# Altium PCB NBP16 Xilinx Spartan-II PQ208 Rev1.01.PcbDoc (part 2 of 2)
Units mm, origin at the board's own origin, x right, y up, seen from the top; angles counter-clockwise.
Board outline 69 x 80.99 mm, 2 copper layers (Top Layer, Bottom Layer); 48 components, 186 nets, 518 pads, 188 vias.
Unrouted connection lines stored in the file: 1.
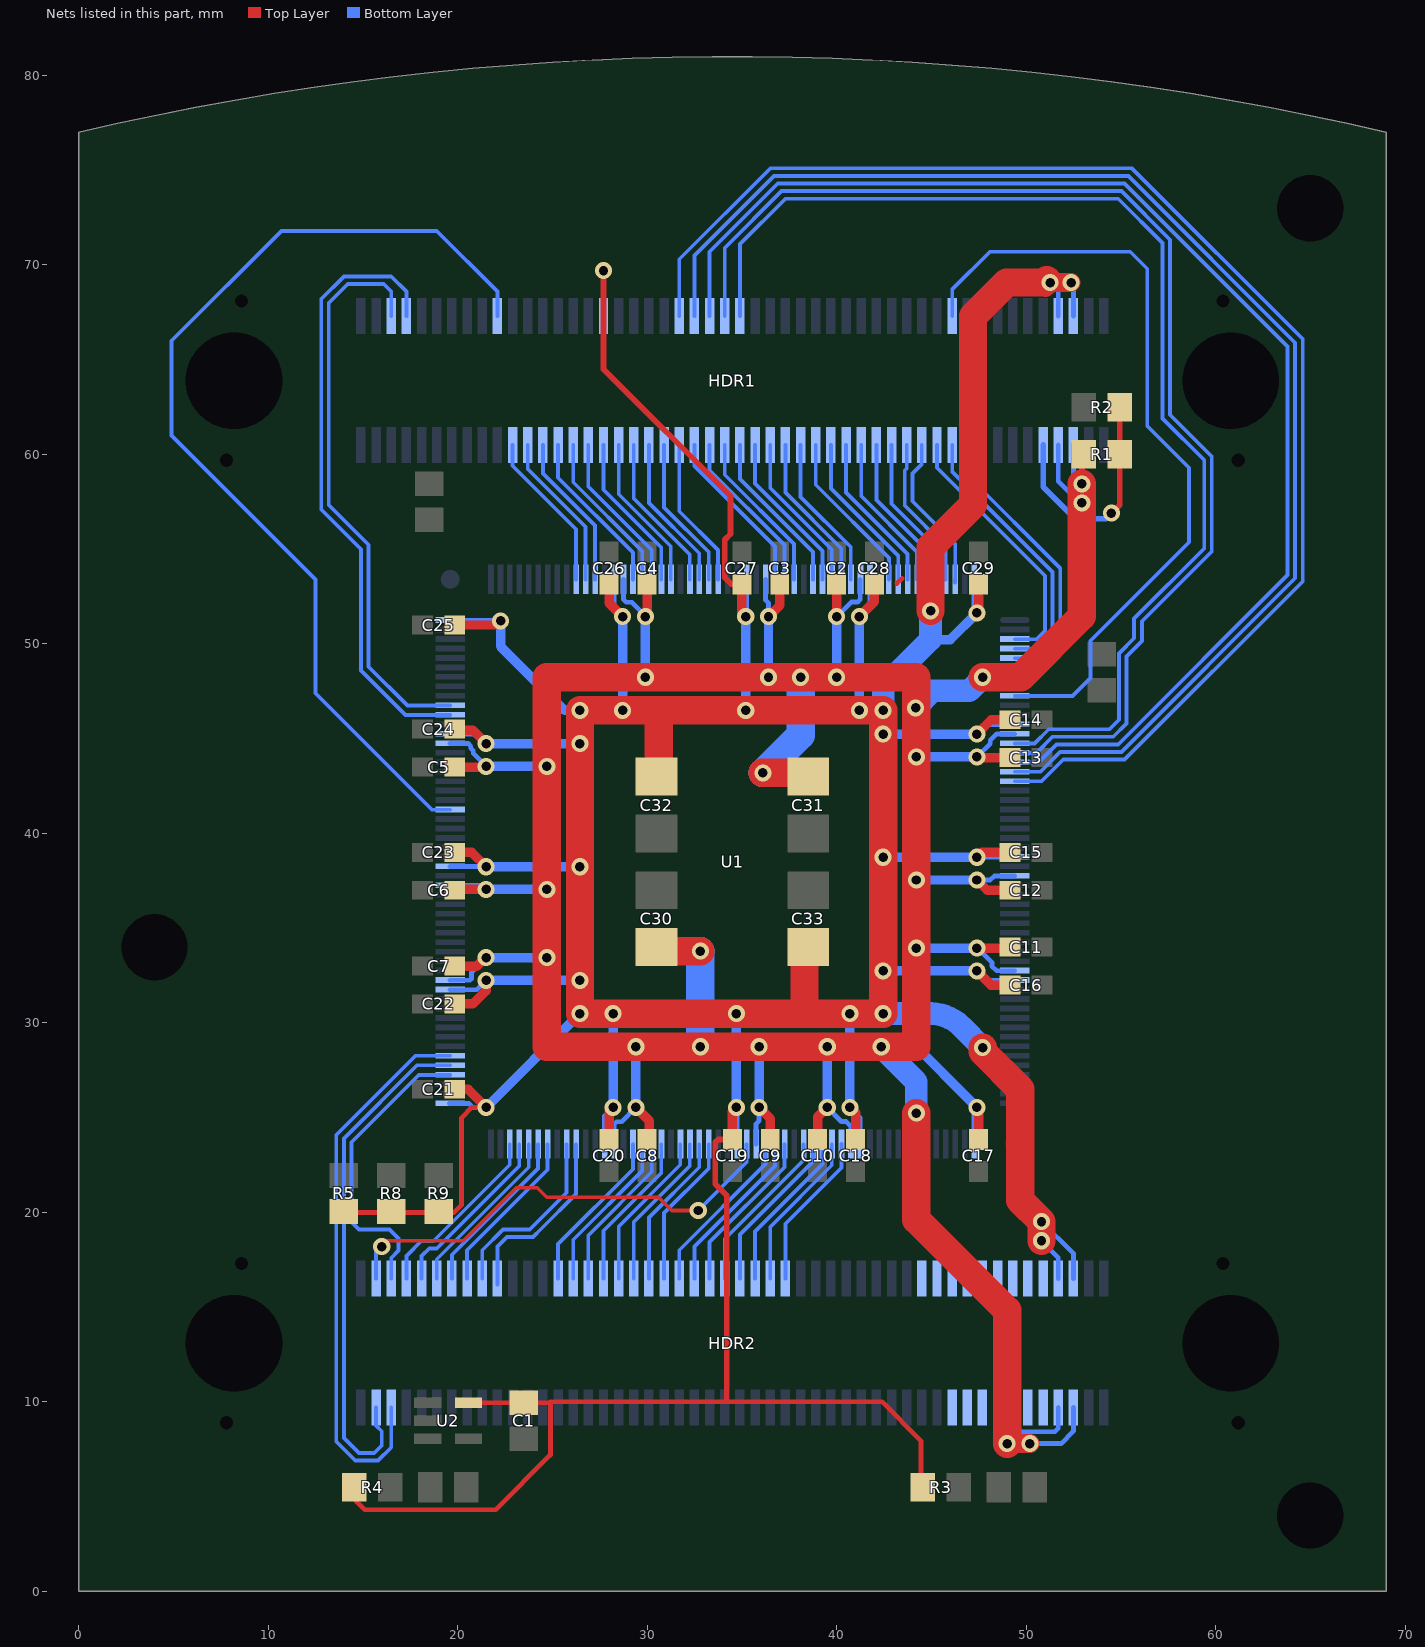
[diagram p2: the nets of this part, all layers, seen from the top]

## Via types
v1: diameter 0.9, hole 0.5, Top Layer to Bottom Layer, tented both sides, 188 vias

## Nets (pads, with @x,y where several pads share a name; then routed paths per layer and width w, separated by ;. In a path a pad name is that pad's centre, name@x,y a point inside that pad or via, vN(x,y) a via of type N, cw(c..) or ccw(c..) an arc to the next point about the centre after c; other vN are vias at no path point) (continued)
NEXUS_TMS: HDR1.80 U1.9 | length 42
  Bottom Layer w0.2: HDR1.80@46.1,67.3 46.1,68.7 48.1,70.7 55.5,70.7 56.4,69.8 56.4,61.5 58.6,59.3 58.6,55.369 53.4,50.169 53.4,48.2 52.45,47.25 U1.9@49.4,47.25
RAM0_DATA0: HDR2.42 U1.81 | length 8.1
  Bottom Layer w0.2: HDR2.42@30.9,16.5 30.9,19.966 33.25,22.316 U1.81@33.25,23.6
RAM0_DATA1: HDR2.40 U1.82 | length 8.2
  Bottom Layer w0.2: HDR2.40@30.1,16.5 30.1,19.731 32.75,22.381 U1.82@32.75,23.6
RAM0_DATA2: HDR2.38 U1.83 | length 8.3
  Bottom Layer w0.2: HDR2.38@29.3,16.5 29.3,19.497 32.25,22.447 U1.83@32.25,23.6
RAM0_DATA3: HDR2.36 U1.84 | length 8.4
  Bottom Layer w0.2: HDR2.36@28.5,16.5 28.5,19.263 31.75,22.513 U1.84@31.75,23.6
RAM0_DATA4: HDR2.34 U1.86 | length 8.4
  Bottom Layer w0.2: HDR2.34@27.7,16.5 27.7,19.028 30.75,22.078 U1.86@30.75,23.6
RAM0_DATA5: HDR2.32 U1.87 | length 8.5
  Bottom Layer w0.2: HDR2.32@26.9,16.5 26.9,18.794 30.25,22.144 U1.87@30.25,23.6
RAM0_DATA6: HDR2.30 U1.88 | length 8.6
  Bottom Layer w0.2: HDR2.30@26.1,16.5 26.1,18.56 29.75,22.21 U1.88@29.75,23.6
RAM0_DATA7: HDR2.28 U1.89 | length 8.7
  Bottom Layer w0.2: HDR2.28@25.3,16.5 25.3,18.325 29.25,22.275 U1.89@29.25,23.6
RAM0_OE: HDR1.41 U1.180 | length 8.1
  Bottom Layer w0.2: HDR1.41@30.9,60.5 30.9,57.2 33.25,54.85 U1.180@33.25,53.4
RAM0_WE: HDR1.79 U1.4 | length 14.5
  Bottom Layer w0.2: HDR1.79@46.1,60.5 46.1,59.1 51.4,53.8 51.4,50.5 50.65,49.75 U1.4@49.4,49.75
RAM1_DATA0: HDR1.45 U1.187 | length 8.9
  Bottom Layer w0.2: HDR1.45@32.5,60.5 32.5,59.4 36.75,55.15 U1.187@36.75,53.4
RAM1_DATA1: HDR1.49 U1.189 | length 8.6
  Bottom Layer w0.2: HDR1.49@34.1,60.5 34.1,58.931 37.75,55.281 U1.189@37.75,53.4
RAM1_DATA2: HDR1.53 U1.192 | length 8.6
  Bottom Layer w0.2: HDR1.53@35.7,60.5 35.7,58.463 39.25,54.913 U1.192@39.25,53.4
RAM1_DATA3: HDR1.57 U1.194 | length 8.3
  Bottom Layer w0.2: HDR1.57@37.3,60.5 37.3,57.994 40.25,55.044 U1.194@40.25,53.4
RAM1_DATA4: HDR1.55 U1.193 | length 8.4
  Bottom Layer w0.2: HDR1.55@36.5,60.5 36.5,58.228 39.75,54.978 U1.193@39.75,53.4
RAM1_DATA5: HDR1.51 U1.191 | length 8.7
  Bottom Layer w0.2: HDR1.51@34.9,60.5 34.9,58.697 38.75,54.847 U1.191@38.75,53.4
RAM1_DATA6: HDR1.47 U1.188 | length 8.7
  Bottom Layer w0.2: HDR1.47@33.3,60.5 33.3,59.166 37.25,55.216 U1.188@37.25,53.4
RAM1_DATA7: HDR1.43 U1.181 | length 7.9
  Bottom Layer w0.2: HDR1.43@31.7,60.5 31.7,57 33.75,54.95 U1.181@33.75,53.4
RAM1_OE: HDR1.39 U1.179 | length 8.2
  Bottom Layer w0.2: HDR1.39@30.1,60.5 30.1,57.434 32.75,54.784 U1.179@32.75,53.4
RAM1_WE: HDR1.61 U1.199 | length 8.7
  Bottom Layer w0.2: HDR1.61@38.9,60.5 38.9,58.4 42.76,54.54 U1.199@42.76,53.411 ; U1.199@42.75,53.4 U1.199@42.75,53.411
RAM_ADDR0: HDR1.21 U1.166 | length 8.5
  Bottom Layer w0.2: HDR1.21@22.9,60.5 22.9,59.4 26.25,56.05 U1.166@26.25,53.4
RAM_ADDR1: HDR1.25 U1.168 | length 8.2
  Bottom Layer w0.2: HDR1.25@24.5,60.5 24.5,59 27.25,56.25 U1.168@27.25,53.4
RAM_ADDR2: HDR1.29 U1.173 | length 8.6
  Bottom Layer w0.2: HDR1.29@26.1,60.5 26.1,58.534 29.75,54.884 U1.173@29.75,53.4
RAM_ADDR3: HDR1.33 U1.175 | length 8.4
  Bottom Layer w0.2: HDR1.33@27.7,60.5 27.7,58.137 30.75,55.087 U1.175@30.75,53.4
RAM_ADDR4: HDR1.65 U1.201 | length 8.4
  Bottom Layer w0.2: HDR1.65@40.5,60.5 40.5,58 43.75,54.75 U1.201@43.75,53.4
RAM_ADDR5: HDR1.69 U1.203 | length 8.2
  Bottom Layer w0.2: HDR1.69@42.1,60.5 42.1,57.6 44.75,54.95 U1.203@44.75,53.4
RAM_ADDR6: HDR1.73 U1.205 | length 8
  Bottom Layer w0.2: HDR1.73@43.7,60.5 43.7,59.266 43.6,59.166 43.6,57.3 45.75,55.15 U1.205@45.75,53.4
RAM_ADDR7: HDR1.77 U1.3 | length 13.9
  Bottom Layer w0.2: HDR1.77@45.3,60.5 45.3,59.3 51,53.6 51,50.7 50.55,50.25 U1.3@49.4,50.25
RAM_ADDR8: HDR1.75 U1.206 | length 8.4
  Bottom Layer w0.2: HDR1.75@44.5,60.5 44.5,59.5 44,59 44,57.534 46.26,55.275 U1.206@46.26,53.411 ; U1.206@46.25,53.25 U1.206@46.25,53.411
RAM_ADDR9: HDR1.71 U1.204 | length 8.1
  Bottom Layer w0.2: HDR1.71@42.9,60.5 42.9,57.4 45.25,55.05 U1.204@45.25,53.4
RAM_ADDR10: HDR1.67 U1.202 | length 8.3
  Bottom Layer w0.2: HDR1.67@41.3,60.5 41.3,57.8 44.25,54.85 U1.202@44.25,53.4
RAM_ADDR11: HDR1.63 U1.200 | length 8.6
  Bottom Layer w0.2: HDR1.63@39.7,60.5 39.7,58.2 43.26,54.64 U1.200@43.26,53.411 ; U1.200@43.25,53.4 U1.200@43.25,53.411
RAM_ADDR12: HDR1.59 U1.195 | length 8.2
  Bottom Layer w0.2: HDR1.59@38.1,60.5 38.1,57.76 40.75,55.11 U1.195@40.75,53.4
RAM_ADDR13: HDR1.35 U1.176 | length 8.2
  Bottom Layer w0.2: HDR1.35@28.5,60.5 28.5,57.903 31.25,55.153 U1.176@31.25,53.4
RAM_ADDR14: HDR1.31 U1.174 | length 8.5
  Bottom Layer w0.2: HDR1.31@26.9,60.5 26.9,58.3 30.25,54.95 U1.174@30.25,53.4
RAM_ADDR15: HDR1.27 U1.172 | length 8.7
  Bottom Layer w0.2: HDR1.27@25.3,60.5 25.3,58.769 29.25,54.819 U1.172@29.25,53.4
RAM_ADDR16: HDR1.23 U1.167 | length 8.4
  Bottom Layer w0.2: HDR1.23@23.7,60.5 23.7,59.234 26.75,56.184 U1.167@26.75,53.4
RAM_CS: HDR1.37 U1.178 | length 8.3
  Bottom Layer w0.2: HDR1.37@29.3,60.5 29.3,57.669 32.25,54.719 U1.178@32.25,53.4
RED0: HDR1.6 U1.147 | length 30.4
  Bottom Layer w0.2: HDR1.6@16.5,67.3 16.5,68.6 16.1,69 14.2,69 13.2,68 13.2,57.334 15.3,55.234 15.3,48.8 17.35,46.75 U1.147@19.6,46.75
RED1: HDR1.8 U1.146 | length 32.8
  Bottom Layer w0.2: HDR1.8@17.3,67.3 17.3,68.6 16.5,69.4 14,69.4 12.8,68.2 12.8,57.1 14.9,55 14.9,48.6 17.25,46.25 U1.146@19.6,46.25
REF_CLK: HDR2.4 U1.77 | length 24.9
  Top Layer w0.2: v1(15.996,18.196) 16.3,18.5 20.3,18.5 20.7,18.9 23.1,21.3 24.2,21.3 24.7,20.8 30.6,20.8 31.3,20.1 v1(32.7,20.1)
  Bottom Layer w0.2: HDR2.4@15.7,16.5 15.7,17.9 v1(15.996,18.196) ; v1(32.7,20.1) 35.25,22.65 U1.77@35.25,23.6
SCL: HDR2.5 U1.110 | length 29.6
  Bottom Layer w0.2: HDR2.5@16.5,9.7 16.5,7.6 15.8,6.9 14.6,6.9 13.6,7.9 13.6,24.1 17.761,28.261 U1.110@19.61,28.261
SDA: HDR2.3 U1.109 | length 27.6
  Bottom Layer w0.2: HDR2.3@15.7,9.7 15.7,8.75 16,8.45 16,7.7 15.6,7.3 14.8,7.3 14,8.1 14,23.9 17.861,27.761 U1.109@19.61,27.761
SP0: HDR2.79
SP1: HDR2.81
SP2: HDR2.83
SP3: HDR2.85
SP4: HDR2.87
SP5: HDR2.89
SP6: HDR2.91
SP7: HDR2.90
SP8: HDR2.92
SP9: HDR2.88
SP10: HDR2.86
SP11: HDR2.84
SP12: HDR2.82
SP13: HDR2.80
SP14: HDR2.78
SP15: HDR2.76
SPI_CLK: HDR1.46 U1.17 | length 71.8
  Bottom Layer w0.2: HDR1.46@32.5,67.3 32.5,70.5 36.7,74.7 55.4,74.7 64.2,65.9 64.2,53.466 55.034,44.3 51.8,44.3 50.75,43.25 U1.17@49.4,43.25
SPI_DIN: HDR1.44 U1.18 | length 74
  Bottom Layer w0.2: HDR1.44@31.7,67.3 31.7,70.3 36.5,75.1 55.6,75.1 64.6,66.1 64.6,53.3 55.2,43.9 51.966,43.9 50.816,42.75 U1.18@49.4,42.75
SPI_DOUT: HDR1.50 U1.15 | length 64.3
  Bottom Layer w0.2: HDR1.50@34.1,67.3 34.1,70.9 37.1,73.9 55.034,73.9 57.6,71.334 57.6,62.1 59.8,59.9 59.8,54.872 56.126,51.197 56.126,50.16 55.3,49.334 55.3,45.8 54.6,45.1 51.4,45.1 50.55,44.25 U1.15@49.4,44.25
SPI_MODE: HDR1.52 U1.14 | length 62
  Bottom Layer w0.2: HDR1.52@34.9,67.3 34.9,71.1 37.3,73.5 54.869,73.5 57.2,71.169 57.2,61.9 59.4,59.7 59.4,55.037 55.7,51.337 55.7,50.3 54.9,49.5 54.9,46 54.4,45.5 51.2,45.5 50.45,44.75 U1.14@49.4,44.75
SPI_SEL: HDR1.48 U1.16 | length 69.5
  Bottom Layer w0.2: HDR1.48@33.3,67.3 33.3,70.7 36.9,74.3 55.2,74.3 63.8,65.7 63.8,53.631 54.869,44.7 51.6,44.7 50.65,43.75 U1.16@49.41,43.75
SW0: HDR2.44 U1.75 | length 9
  Bottom Layer w0.2: HDR2.44@31.7,16.5 31.7,18 36.25,22.55 U1.75@36.25,23.6
SW1: HDR2.46 U1.74 | length 8.9
  Bottom Layer w0.2: HDR2.46@32.5,16.5 32.5,18.2 36.75,22.45 U1.74@36.75,23.6
SW2: HDR2.48 U1.73 | length 8.7
  Bottom Layer w0.2: HDR2.48@33.3,16.5 33.3,18.434 37.25,22.384 U1.73@37.25,23.6
SW3: HDR2.50 U1.71 | length 8.8
  Bottom Layer w0.2: HDR2.50@34.1,16.5 34.1,18.6 38.25,22.75 U1.71@38.25,23.6
SW4: HDR2.52 U1.70 | length 8.7
  Bottom Layer w0.2: HDR2.52@34.9,16.5 34.9,18.834 38.75,22.684 U1.70@38.75,23.6
SW5: HDR2.54 U1.69 | length 8.6
  Bottom Layer w0.2: HDR2.54@35.7,16.5 35.7,19 39.25,22.55 U1.69@39.25,23.6
SW6: HDR2.56 U1.68 | length 8.4
  Bottom Layer w0.2: HDR2.56@36.5,16.5 36.5,19.234 39.75,22.484 U1.68@39.75,23.6
SW7: HDR2.58 U1.67 | length 8.3
  Bottom Layer w0.2: HDR2.58@37.3,16.5 37.3,19.4 40.26,22.36 U1.67@40.26,23.611
SWC0: HDR2.18 U1.96 | length 9.8
  Bottom Layer w0.2: HDR2.18@21.3,16.5 21.3,18 22.4,19.1 23.812,19.1 25.75,21.038 U1.96@25.75,23.6
SWC1: HDR2.16 U1.98 | length 8.9
  Bottom Layer w0.2: HDR2.16@20.5,16.5 20.5,18 24.75,22.25 U1.98@24.75,23.6
SWC2: HDR2.14 U1.99 | length 9
  Bottom Layer w0.2: HDR2.14@19.7,16.5 19.7,17.766 24.25,22.316 U1.99@24.25,23.6
SWC3: HDR2.6 U1.108 | length 16
  Bottom Layer w0.2: HDR2.6@16.5,16.5 16.5,17.6 16.885,17.985 16.885,18.615 16.4,19.1 14.8,19.1 14.4,19.5 14.4,23.7 17.95,27.25 U1.108@19.6,27.25
SWR0: HDR2.20 U1.95 | length 9.9
  Bottom Layer w0.2: HDR2.20@22.1,16.2 HDR2.20@22.1,16.5 22.1,18.2 22.6,18.7 23.977,18.7 24.412,19.135 26.25,20.973 U1.95@26.25,23.6
SWR1: HDR2.12 U1.100 | length 9.1
  Bottom Layer w0.2: HDR2.12@18.9,16.5 18.9,17.531 23.75,22.381 U1.100@23.75,23.6
SWR2: HDR2.10 U1.101 | length 9.5
  Bottom Layer w0.2: HDR2.10@18.1,16.5 18.1,17.7 18.5,18.1 18.903,18.1 23.25,22.447 U1.101@23.25,23.6
SWR3: HDR2.8 U1.102 | length 9.7
  Bottom Layer w0.2: HDR2.8@17.3,16.5 17.3,17.7 18.1,18.5 18.737,18.5 22.75,22.513 U1.102@22.75,23.6
TEST: HDR1.81 U1.5 | length 15.1
  Bottom Layer w0.2: HDR1.81@46.9,60.5 46.9,58.9 51.8,54 51.8,50.3 50.75,49.25 U1.5@49.4,49.25
VCC: C1.2 C14.1 C15.1 C16.1 C17.2 C18.2 C19.2 C20.2 C21.2 C22.1 C23.1 C24.1 C25.2 C26.2 C27.2 C28.2 C29.2 C32.1 C33.1 HDR1.34 HDR1.94 HDR1.96 HDR2.94 HDR2.96 R3.1 R4.2 R5.1 R8.1 R9.1 U1.12 U1.26 U1.39 U1.53 U1.65 U1.78 U1.92 U1.105 U1.117 U1.130 U1.144 U1.156 U1.170 U1.184 U1.197 U1.208 U2.5 | length 368.1
  Top Layer w0.25: R5.1@13.708,19.992 19.808,19.992 20.208,20.392 20.208,24.992 20.758,25.542 v1(21.508,25.542) ; R4.2@14.55,5.497 14.55,4.85 15.1,4.3 22,4.3 24.9,7.2 24.9,10 ; U2.5@20.575,9.95 C1.2@23.497,9.95 24.85,9.95 24.9,10 ; 43.189,53.192 43.449,53.452 ; R3.1@44.45,5.5 R3.1@44.45,5.503 ; R3.1@44.55,5.503 44.45,5.602 44.45,7.95 42.4,10 24.9,10
  Top Layer w0.3: v1(27.7,69.7) 27.701,64.499 34.4,57.8 34.4,55.8 34.1,55.5 34.1,53.5 34.45,53.15 C27.2@35,53.15 ; 34.2,10.05 34.2,20.9 33.6,21.5 33.6,23.7 33.75,23.85 C19.2@34.5,23.85
  Top Layer w0.5: C24.1@19.758,45.442 20.808,45.442 v1(21.508,44.742) ; C21.2@19.85,26.5 20.55,26.5 v1(21.508,25.542) ; C22.1@19.85,31 20.8,31 21.508,31.708 v1(21.508,32.242) ; C23.1@19.85,39 20.75,39 v1(21.508,38.242) ; C25.2@19.85,51 22.048,51 v1(22.265,51.217) ; C20.2@28,23.85 28,25.334 v1(28.208,25.542) ; C26.2@28.008,53.192 28.008,52.142 v1(28.708,51.442) ; C19.2@34.5,23.85 34.5,25.334 v1(34.708,25.542) ; C27.2@35,53.15 35,51.65 v1(35.208,51.442) ; v1(40.708,25.542) 41,25.25 C18.2@41,23.85 ; v1(41.208,51.442) 42,52.234 C28.2@42,53.15 ; v1(47.408,25.542) 47.5,25.45 C17.2@47.5,23.85 ; v1(47.408,32.742) 48.15,32 C16.1@49.15,32 ; v1(47.408,38.742) 47.666,39 C15.1@49.15,39 ; v1(47.408,45.242) 48.166,46 C14.1@49.15,46 ; v1(47.408,51.642) 47.5,51.734 C29.2@47.5,53.15
  Top Layer w1: v1@51.018,68.819 51.25,69.05 v1(51.275,69.075) v1(52.375,69.075)
  Top Layer w1.5: C32.1@30.608,43.192 30.608,46.492 ; 38.308,30.492 C33.1@38.308,33.792 ; v1(44.958,51.742) 44.958,55.098 47.2,57.34 47.2,67.3 48.975,69.075 50.975,69.075 v1@51.1,69.2 ; v1(47.708,28.692) 47.708,28.489 49.7,26.497 49.7,20.633 v1(50.815,19.518) v1(50.815,18.502) ; v1(26.458,30.492) v1(42.458,30.492) v1(42.458,46.492) v1(26.458,46.492) v1(26.458,30.492)
  Bottom Layer w0.25: U1.105@19.558,25.742 20.608,25.742 20.808,25.542 v1(21.508,25.542) ; U1.117@19.6,31.75 21.016,31.75 v1(21.508,32.242) ; U1.130@19.6,38.25 21.5,38.25 v1(21.508,38.242) ; U1.144@19.6,45.25 21,45.25 v1(21.508,44.742) ; U1.156@19.6,51.25 22.233,51.25 v1(22.265,51.217) v1@21.96,51.242 ; HDR1.34@27.7,67.3 v1(27.7,69.7) ; U1.92@27.75,23.6 27.75,25.084 v1(28.208,25.542) ; U1.170@28.25,53.4 28.25,51.9 v1(28.708,51.442) ; v1(34.708,25.542) 34.75,25.5 U1.78@34.75,23.6 ; v1(35.208,51.442) 35.25,51.484 U1.184@35.25,53.4 ; v1(40.708,25.542) 41.25,25 U1.65@41.25,23.6 ; v1(41.208,51.442) 41.75,51.984 U1.197@41.75,53.4 ; U1.53@47.25,23.6 47.25,25.384 v1(47.408,25.542) ; U1.208@47.25,53.4 47.25,51.8 v1(47.408,51.642) ; v1(47.408,32.742) 47.9,32.25 U1.39@49.4,32.25 ; v1(47.408,38.742) U1.26@49.392,38.742 ; v1(47.408,45.242) 47.916,45.75 U1.12@49.4,45.75 ; v1(50.815,18.502) 51.7,17.617 HDR2.94@51.7,16.5 ; v1(50.815,19.518) 52.5,17.833 HDR2.96@52.5,16.5 ; v1(51.275,69.075) 51.7,68.65 HDR1.94@51.7,67.3 ; v1(52.375,69.075) 52.5,68.95 HDR1.96@52.5,67.3
  Bottom Layer w0.5: v1(21.508,25.542) v1(26.458,30.492) ; v1(21.508,32.242) v1(26.458,32.242) ; v1(21.508,38.242) v1(26.458,38.242) ; v1(21.508,44.742) v1(26.458,44.742) ; v1(22.265,51.217) 22.265,49.871 25.644,46.492 v1(26.458,46.492) ; v1(28.208,25.542) v1(28.208,30.492) ; v1(28.708,46.492) v1(28.708,51.442) ; v1(34.708,25.542) v1(34.708,30.492) ; v1(35.208,46.492) v1(35.208,51.442) ; v1(40.708,25.542) v1(40.708,30.492) ; v1(41.208,46.492) v1(41.208,51.442) ; v1(42.458,32.742) v1(47.408,32.742) ; v1(42.458,38.742) v1(47.408,38.742) ; v1(42.458,45.242) v1(47.408,45.242) ; 43.808,30.492 43.808,29.142 v1(47.408,25.542) ; 44.958,50.233 45.999,50.233 v1(47.408,51.642)
  Bottom Layer w1.2: v1(42.458,30.492) 44.955,30.492 cw(c44.955,28.192) 46.582,29.819 v1(47.708,28.692) ; v1(42.458,46.492) 42.458,47.733 44.958,50.233 v1(44.958,51.742)
VCCINT: C2.1 C3.1 C4.1 C5.1 C6.1 C7.1 C8.1 C9.1 C10.1 C11.1 C12.1 C13.1 C30.1 C31.1 HDR1.93 HDR1.95 HDR2.93 HDR2.95 R1.1 U1.13 U1.28 U1.38 U1.66 U1.76 U1.91 U1.118 U1.128 U1.143 U1.171 U1.186 U1.196 | length 244.3
  Top Layer w0.3: v1(52.95,58.45) 52.95,59.903 R1.1@53.05,60.003
  Top Layer w0.5: C7.1@19.85,33 21.022,33 v1@21.465,33.442 ; C6.1@19.85,37 19.892,37.042 v1(21.508,37.042) ; C5.1@19.85,43.5 21.466,43.5 v1(21.508,43.542) ; v1(29.408,25.542) 30.108,24.842 C8.1@30.108,23.792 ; v1(29.908,51.442) 30,51.534 C4.1@30,53.15 ; v1(35.908,25.542) 36.5,24.95 C9.1@36.5,23.85 ; v1(36.408,51.442) 37,52.034 C3.1@37,53.15 ; C10.1@39,23.85 39,25.034 v1(39.508,25.542) ; v1@40,51.45 C2.1@40,53.15 ; v1(47.408,33.942) 49.092,33.942 C11.1@49.15,34 ; v1(47.408,37.542) 47.95,37 C12.1@49.15,37 ; v1(47.408,44.042) 47.45,44 C13.1@49.15,44
  Top Layer w1: v1@48.783,8.037 v1(49,7.8) v1(50.2,7.8)
  Top Layer w1.5: C30.1@30.608,33.792 v1(32.808,33.792) ; v1(36.108,43.192) C31.1@38.308,43.192 ; v1(44.208,25.242) 44.208,19.623 49,14.831 v1(49,7.8) ; v1(47.708,48.242) 49.72,48.242 52.95,51.473 v1(52.95,58.45) ; 24.708,28.742 44.208,28.742 44.208,48.242 24.708,48.242 24.708,28.742
  Bottom Layer w0.25: U1.118@19.6,32.25 20.65,32.25 20.739,32.339 20.739,32.673 v1(21.508,33.442) ; U1.128@19.6,37.25 21.3,37.25 v1(21.508,37.042) ; U1.143@19.6,44.75 20.55,44.75 20.7,44.6 20.7,44.5 20.826,44.374 20.826,44.224 v1(21.508,43.542) v1@21.458,43.542 ; U1.91@28.25,23.6 28.25,24.65 28.389,24.789 28.654,24.789 v1(29.408,25.542) ; U1.171@28.75,53.4 28.75,52.35 28.9,52.2 29.2,52.2 29.908,51.492 v1(29.908,51.442) ; U1.76@35.75,23.6 35.75,24.684 35.908,24.842 v1(35.908,25.542) ; U1.186@36.25,53.4 36.25,52.3 36.408,52.142 v1(36.408,51.442) ; v1(40.008,51.442) 40.777,52.211 41.111,52.211 41.25,52.35 U1.196@41.25,53.4 ; 40.208,24.842 v1(39.508,25.542) 40.256,24.794 40.506,24.794 40.75,24.55 U1.66@40.75,23.6 ; v1(47.408,33.942) 47.458,33.942 48.2,33.2 48.2,33 48.45,32.75 U1.38@49.4,32.75 ; v1(47.408,37.542) 48.108,37.542 48.316,37.75 U1.28@49.4,37.75 ; v1(47.408,44.042) 48.106,44.741 48.106,44.906 48.45,45.25 U1.13@49.4,45.25 ; v1(49,7.8) 49.65,8.425 51.525,8.425 51.7,8.6 HDR2.93@51.7,9.7 ; v1(50.2,7.8) 51.85,7.8 52.5,8.45 HDR2.95@52.5,9.7 ; 51.7,59.3 HDR1.93@51.7,60.5 51.7,58.575 52.75,57.525 v1(52.949,57.44) ; 52.5,59.425 HDR1.95@52.5,60.5 52.5,58.9 v1(52.95,58.45)
  Bottom Layer w0.5: v1(21.508,33.442) v1(24.708,33.442) ; v1(21.508,37.042) v1(24.708,37.042) ; v1(21.508,43.542) v1(24.708,43.542) ; v1(29.408,25.542) v1(29.408,28.742) ; v1(29.908,48.242) v1(29.908,51.442) ; v1(35.908,25.542) v1(35.908,28.742) ; v1(36.408,48.242) v1(36.408,51.442) ; v1(39.508,25.542) v1(39.508,28.742) ; v1(40.008,48.242) v1(40.008,51.442) ; v1(44.208,33.942) v1(47.408,33.942) ; v1(44.208,37.542) v1(47.408,37.542) ; v1(44.208,44.042) v1(47.408,44.042)
  Bottom Layer w1.2: v1(42.358,28.742) 44.208,26.892 v1(44.208,25.242) ; v1(44.175,46.625) 45.05,47.525 47,47.525 v1(47.708,48.242)
  Bottom Layer w1.5: v1(32.808,28.742) v1(32.808,33.792) ; v1(36.108,43.192) 38.108,45.192 v1(38.108,48.242)
VDRIVE: HDR1.20 U1.136 | length 53.6
  Bottom Layer w0.2: U1.136@19.6,41.25 18.65,41.25 12.5,47.4 12.5,53.4 4.9,61 4.9,66 10.7,71.8 18.9,71.8 22.1,68.6 HDR1.20@22.1,67.3
VREF: HDR1.91 R1.2 R2.1 | length 12.4
  Top Layer w0.3: v1(54.5,56.9) 54.95,57.35 R2.1@54.95,62.497
  Bottom Layer w0.3: HDR1.91@50.9,60.5 50.9,58.3 52.6,56.6 54.2,56.6 v1(54.5,56.9)
pads on no net: HDR1.MH1 HDR1.MH2 HDR1.MH3 HDR1.MH4 HDR1.MH5 HDR1.MH6 HDR2.MH1 HDR2.MH2 HDR2.MH3 HDR2.MH4 HDR2.MH5 HDR2.MH6 U1.55 U1.56 U1.60 U1.149 U1.FID1 U1.FID2 U2.1

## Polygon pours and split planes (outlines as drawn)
GND on Top Layer "Top Layer-GND" (solid, remove dead copper, pour order 1000): 0,0 0,82.2 69,82.2 69,0
GND on Bottom Layer "Bottom Layer-GND" (solid, remove dead copper, pour order 1001): 0,0 0,82.1 69,82.1 69,0

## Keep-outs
Keep-Out Layer:
  the board outline again, w0.8

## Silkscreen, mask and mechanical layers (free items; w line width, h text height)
Top Overlay:
  circle w0.127: c65,73 r2.5
  circle w0.127: c65,4 r2.5
  circle w0.127: c4,34 r2.5
  lines w0.127: 0,1.5 1.5,1.5 1.5,0 ; 0,22.3 1.5,22.3 1.5,23.4 0,23.4 ; 0.001,53.6 1.501,53.6 1.501,54.7 0.001,54.7 ; 0,75.5 1.5,75.5 1.5,77.3 ; 15.7,79.8 15.7,78.1 17,78.1 17,79.9 ; 49.7,80.2 49.7,78.7 51,78.7 51,80.1 ; 67.5,0 67.5,1.5 69,1.5 ; 67.5,77.3 67.5,75.5 69,75.5 ; 68.999,22.3 67.5,22.3 67.5,23.4 69,23.4 ; 69,53.6 67.501,53.6 67.501,54.7 69.001,54.7
Bottom Overlay:
  drawing of 853 lines, arcs and shapes, not listed
  text "REV 1.01" at 47.6,76.5 h1.3
  text "NBP16" at 54.981,76.481 h1.3
  text "1" at 13.97,58.42 h1
  text "1" at 14.224,7.62 h1
PCB Boundary:
  the board outline again, w0.25
  text "PCB boundary coincides with centre-line of tracks and arc" at 0,-12 h0.75
Gerber ID:
  text ".Layer_Name" at 0,-6 h0.75
Printout ID:
  text ".Printout_Name" at 0,-10 h0.75
Design Information:
  drawing of 713 lines, arcs and shapes, not listed
  text "NBP16 REV 1.01" at 317.627,202.041 h1.27
  text "DESIGN INFORMATION" at 261.62,201.914 h1.52
  text "BOARD NAME:" at 299.212,201.914 h1.52
  text "BOARD TECHNOLOGY" at 261.62,199.374 h1.52
  text "BOARD SIZE (REFER ALSO PROFILING INFORMATION)" at 309.88,199.374 h1.27
  text "69.00mm" at 312.6,197.1 h1.52
  text "11.811" at 277.419,197.012 h1.52
  text "81.00mm" at 335.6,197 h1.52
  text "7.874" at 291.389,196.885 h1.52
  text "7.874" at 264.446,196.834 h1.52
  text "X" at 328.549,196.326 h1.78
  text "(MIN. TRACK/   PADS  /   CLEARANCE     IN 0.001'')" at 260.096,194.294 h1.27
  text "MINIMUM ANNULAR RING 0.05MM (0.002'') EXTERNAL PER IPC-2221 CLASS 3 LEVEL C AND IS THE" at 261.62,191.754 h1.27
  text "MANUFACTURING REGISTRATION ALLOWANCE" at 261.62,189.468 h1.27
  text "LAND SIZE CALCULATION MINIMUM - NOMINAL HOLE SIZE + 0.508MM (0.020'')" at 261.62,186.674 h1.27
  text "AS INSTRUCTED" at 347.65,182.28 h1.52
  text "X" at 299.263,182.153 h1.52
  text "CIRCUIT TYPE:" at 261.62,182.102 h1.52
  text "SS" at 284.48,182.102 h1.27
  text "DS" at 302.26,182.102 h1.27
  text "X" at 316.865,182.102 h1.52
  text "PTH" at 320.04,182.102 h1.27
  text "ML" at 330.962,182.102 h1.27
  text "No. OFF" at 337.82,182.102 h1.27
  text "FINGER CONNECTOR DIM PER:" at 261.62,179.054 h1.52
  text "AS SHOWN" at 337.82,179.054 h1.27
  text "No. OFF TOTAL" at 278.384,176.26 h1.52
  text "ONE SIDE" at 320.04,176.26 h1.27
  text "BOTH SIDES" at 337.82,176.006 h1.27
  text "VIAS:" at 261.62,173.339 h1.52
  text "NONE" at 273.05,173.339 h1.14
  text "X" at 281.432,173.339 h1.52
  text "FEED THRU'" at 284.48,173.339 h1.14
  text "X" at 299.212,173.339 h1.52
  text "TENTED" at 302.26,173.339 h1.14
  text "UNIQUE DRILL" at 284.48,170.291 h1.14
  text "2 SIZE" at 302.26,170.291 h1.14
  text "BLIND LAYER SEQUENCE" at 320.04,170.291 h1.14
  text "Layer Stack Manager (Protel)" at 297.053,168.005 h1.27
  text "X" at 334.772,168.005 h1.52
  text "AS SHOWN" at 337.82,168.005 h1.27
  text "LAYER CONSTRUCTION PER:" at 261.62,167.878 h1.52
  text "Protel" at 342.646,165.338 h1.27
  text "(PFW)" at 352.933,165.211 h1.27
  text "ARTWORK:" at 261.62,165.084 h1.52
  text "MANUAL" at 284.48,165.084 h1.27
  text "DIGITISED" at 302.26,165.084 h1.27
  text "X" at 316.992,165.084 h1.52
  text "CAD" at 320.04,165.084 h1.27
  text "TYPE" at 330.962,165.084 h1.27
  text "ARTWORK/PATTERN MASTER LIST" at 261.62,160.385 h1.52
  text "DESCRIPTION" at 262.89,157.972 h1.27
  text "DRAWING No./CAD FILE REF." at 281.559,157.972 h1.27
  text "LAYER NAME" at 322.834,157.972 h1.27
  text "GERBER FILE REF" at 343.586,157.896 h1.27
  text "PCB FILE" at 261.366,155.432 h1.27
  text "BOCD_SpartanII_PQ208" at 281.237,155.356 h1.27
  text "PcbDoc" at 312.979,155.356 h1.02
  text "Top Paste Mask" at 321.158,152.892 h1.02
  text "GTP" at 363.779,152.816 h1.27
  text "GERBER FILE" at 261.366,152.765 h1.27
  text "GTO" at 363.728,150.327 h1.27
  text "Top Overlay" at 321.158,150.301 h1.02
  text "GERBER FILE" at 261.366,150.225 h1.27
  text "Top Solder Mask" at 321.158,147.863 h1.02
  text "GTS" at 363.779,147.736 h1.27
  text "GERBER FILE" at 261.366,147.685 h1.27
  text "TOP LAYER" at 321.158,145.272 h1.02
  text "GTL" at 363.779,145.196 h1.27
  text "GERBER FILE" at 261.366,145.145 h1.27
  text "BOTTOMLAYER" at 321.158,142.732 h1.02
  text "GBL" at 363.779,142.656 h1.27
  text "GERBER FILE" at 261.366,142.605 h1.27
  text "Bottom Solder Mask" at 321.158,140.243 h1.02
  text "GBS" at 363.779,140.116 h1.27
  text "GERBER FILE" at 261.366,140.065 h1.27
  text "Bottom Overlay" at 321.158,137.652 h1.02
  text "GBO" at 363.779,137.576 h1.27
  text "GERBER FILE" at 261.366,137.525 h1.27
  text "Bottom Paste Mask" at 321.158,135.163 h1.02
  text "GBP" at 363.779,135.036 h1.27
  text "GERBER FILE" at 261.366,134.985 h1.27
  text "PCB Boundary" at 321.158,132.572 h1.02
  text "GM1" at 363.779,132.496 h1.27
  text "GERBER FILE" at 261.366,132.445 h1.27
  text "APERTURE LIST" at 261.366,130.032 h1.27
  text "APR" at 313.979,129.956 h1.27
  text "DRILL REPORT" at 261.366,127.492 h1.27
  text "DRR" at 313.979,127.416 h1.27
  text "EXCELLON DRILL" at 261.366,124.952 h1.27
  text "TXT" at 313.979,124.876 h1.27
  text "MATERIAL:" at 261.62,99.298 h1.52
  text "GLASS FIBRE EPOXY RESIN NEMA GRADE FR4 (MIL-S-13949H)" at 287.274,99.044 h1.27
  text "X" at 284.607,98.917 h1.52
  text "THICKNESS:" at 269.494,96.123 h1.27
  text "0.8mm" at 287.274,96.123 h1.27
  text "1.2mm" at 304.927,96.123 h1.27
  text "1.6mm" at 322.58,96.123 h1.27
  text "2.4mm" at 340.36,96.123 h1.27
  text "3.2mm" at 358.14,96.123 h1.27
  text "X" at 320.167,95.996 h1.52
  text "TOLERANCE:" at 269.367,93.075 h1.27
  text "IN A/W IPC-D-300G CLASS" at 287.02,93.075 h1.27
  text "3 LEVEL B" at 321.945,93.075 h1.27
  text "OTHER +/-" at 340.36,93.075 h1.27
  text "X" at 284.607,92.948 h1.52
  text "BOW & TWIST:" at 266.954,90.027 h1.27
  text "IN A/W IPC-D-300G CLASS" at 287.02,90.027 h1.27
  text "3 LEVEL B" at 321.945,90.027 h1.27
  text "AS SHOWN" at 340.487,89.9 h1.27
  text "X" at 284.607,89.773 h1.52
  text "COPPER THICKNESS (FINISHED)" at 269.367,86.725 h1.27
  text "OUTER:" at 274.193,84.439 h1.27
  text "18um" at 287.274,84.439 h1.27
  text "35um" at 314.325,84.439 h1.27
  text "70um" at 340.614,84.439 h1.27
  text "X" at 311.582,84.236 h1.52
  text "INNER SIGNAL:" at 265.811,81.391 h1.27
  text "18um" at 287.274,81.391 h1.27
  text "35um" at 314.325,81.391 h1.27
  text "70um" at 340.614,81.391 h1.27
  text "INNER PWR:" at 269.494,78.343 h1.27
  text "18um" at 287.274,78.343 h1.27
  text "35um" at 314.325,78.343 h1.27
  text "70um" at 340.614,78.343 h1.27
  text "STRUCTURE:" at 261.62,75.295 h1.52
  text "REFER" at 287.274,75.295 h1.27
  text "AS PER DRAWING No." at 287.147,72.12 h1.27
  text "AS SHOWN" at 340.487,72.12 h1.27
  text "X" at 337.947,71.993 h1.52
  text "DRILLING:" at 261.62,69.326 h1.52
  text "VIEWED FROM:" at 266.573,67.04 h1.27
  text "COMPONENT SIDE" at 287.274,67.04 h1.14
  text "SOLDER SIDE" at 314.071,67.04 h1.14
  text "X" at 284.607,66.786 h1.52
  text "REFERENCE:" at 268.859,63.992 h1.27
  text "AS SHOWN" at 287.147,63.865 h1.14
  text "PATTERN MASTER LIST" at 314.198,63.865 h1.14
  text "X" at 337.947,63.865 h1.52
  text "NC_DRILL FILES" at 340.487,63.865 h1.14
  text "X" at 284.607,63.738 h1.52
  text "PTH MINIMUM COPPER THICKNESS:" at 274.701,60.944 h1.27
  text "20um" at 314.325,60.944 h1.27
  text "X" at 311.658,60.817 h1.52
  text "OTHER" at 340.487,60.817 h1.27
  text "NPTH:" at 275.209,57.896 h1.27
  text "TENTED" at 287.147,57.769 h1.14
  text "X" at 311.658,57.769 h1.52
  text "PADS REMOVED" at 314.198,57.769 h1.14
  text "REMOVE PADS" at 340.487,57.769 h1.14
  text "X" at 284.607,57.642 h1.52
  text "2nd DRILL" at 287.147,54.721 h1.14
  text "BOTH" at 314.198,54.721 h1.14
  text "AS SHOWN" at 326.517,54.721 h1.14
  text "NONE" at 340.487,54.721 h1.14
  text "BOARD FINISH:" at 261.62,51.8 h1.52
  text "X" at 284.607,51.673 h1.52
  text "ETCHING" at 287.147,51.673 h1.14
  text "REFER PATTERN MASTER LIST" at 314.198,51.673 h1.14
  text "LEGEND / SCREEN PRINT:" at 281.94,48.752 h1.27
  text "NONE" at 314.198,48.625 h1.14
  text "COMPONENT" at 326.517,48.625 h1.14
  text "SOLDER" at 340.487,48.625 h1.14
  text "X" at 323.977,48.498 h1.52
  text "X" at 337.947,48.498 h1.52
  text "COLOUR:" at 272.161,45.704 h1.27
  text "WHITE" at 287.147,45.577 h1.14
  text "YELLOW" at 314.198,45.577 h1.14
  text "OTHER" at 340.487,45.577 h1.14
  text "X" at 284.607,45.45 h1.52
  text "X" at 284.607,42.529 h1.52
  text "LIQUID PHOTOIMAGEABLE" at 287.147,42.529 h1.14
  text "SCREEN PRINT" at 326.517,42.529 h1.14
  text "MATTE" at 287.147,39.481 h1.14
  text "GLOSS" at 299.847,39.481 h1.14
  text "GREEN" at 314.198,39.481 h1.14
  text "BLUE" at 326.517,39.481 h1.14
  text "G/Y" at 340.487,39.481 h1.14
  text "OTHER" at 351.917,39.481 h1.14
  text "X" at 297.18,39.354 h1.52
  text "SOLDER MASK COLOUR:" at 261.62,36.56 h1.14
  text "BLACK" at 287.147,36.433 h1.14
  text "GREEN" at 299.847,36.433 h1.14
  text "YELLOW" at 314.198,36.433 h1.14
  text "BLUE" at 326.517,36.433 h1.14
  text "OTHER" at 340.487,36.433 h1.14
  text "X" at 284.48,36.306 h1.52
  text "TRACK FINISH:" at 261.62,33.512 h1.52
  text "SELECTIVE SOLDER (HASL)" at 287.147,33.385 h1.14
  text "REFLOW SOLDER" at 326.517,33.385 h1.14
  text "SELECTIVE GOLD" at 287.147,30.337 h1.14
  text "um  (AREA" at 314.198,30.337 h1.14
  text "sq. mm)" at 342.011,30.337 h1.14
  text "X" at 284.607,27.289 h1.52
  text "IMMERSION GOLD" at 287.147,27.289 h1.14
  text "OTHER" at 326.517,27.289 h1.14
  text "EDGE BOARD" at 261.62,24.368 h1.52
  text "1.3um HARD GOLD OVER 5um     NICKEL / TIN-NICKEL" at 287.147,24.241 h1.14
  text "CONTACTS:" at 261.62,22.209 h1.52
  text "HARD FINISH GOLDE PLATE" at 287.147,21.193 h1.14
  text "OTHER" at 326.517,21.193 h1.14
  text "AS SHOWN" at 287.147,18.145 h1.14
  text "REFER" at 326.517,18.145 h1.14
  text "PROFILING:" at 261.62,15.097 h1.52
  text "AS DIMENSIONED, MEASURED AND CUT FROM SPECIFIED DATUM." at 287.147,15.097 h1.14
  text "X" at 284.607,14.97 h1.52
  text "REFER PCB BLANK DWG No." at 287.274,12.176 h1.27
  text "USE PROFILE / ROUTE TAPE SUPPLIED (REFER PATTERN MASTER LIST)" at 287.274,9.128 h1.27
  text "SQUARE CUT" at 287.274,6.08 h1.27
  text "N.C. ROUTE" at 305.054,6.08 h1.27
  text "V. SCORE" at 322.834,6.08 h1.27
  text "BLANK" at 340.614,6.08 h1.27
  text "ACCEPTABILITY:" at 261.62,3.413 h1.52
  text "MATERIALS AND WORKMANSHIP FOR ALL PRINTED WIRING BOARDS TO MEET" at 283.845,3.286 h1.27
  text "OR EXCEED THE REQUIREMENTS OF:" at 283.845,0.492 h1.27
  text "IPC-6011/12 AND IPC-A-600E" at 287.401,-2.175 h1.27
  text "1" at 322.961,-2.175 h1.27
  text "2" at 331.851,-2.175 h1.27
  text "X" at 329.184,-2.302 h1.52
  text "X" at 284.734,-2.429 h1.52
  text "3" at 340.741,-4.334 h1.27
  text "UL CERTIFICATION" at 287.401,-5.223 h1.27
  text "AUSTEL" at 322.961,-5.223 h1.27
  text "X" at 284.734,-5.35 h1.52
  text "ML-P-55110F GRP" at 286.893,-8.271 h1.02
  text "A" at 305.181,-8.271 h1.27
  text "B" at 314.071,-8.271 h1.27
  text "AS2546" at 322.961,-8.271 h1.27
  text "OTHER" at 340.741,-8.271 h1.27
  text "ADDITIONAL" at 261.62,-11.192 h1.52
  text "NONE" at 287.401,-11.446 h1.27
  text "SAMPLE PLAN" at 305.181,-11.446 h1.27
  text "MIL-P-55110E SERIAL Nos. PER ORDER" at 322.961,-11.446 h1.27
  text "REQUIREMENTS:" at 261.62,-13.605 h1.52
  text "NONE" at 287.401,-14.494 h1.27
  text "ML-P-55110F GRP" at 304.673,-14.494 h1.02
  text "A" at 322.961,-14.494 h1.27
  text "B" at 331.851,-14.494 h1.27
  text "IPC CLASS:" at 337.82,-14.494 h1.27
  text "1" at 353.314,-14.494 h1.27
  text "2" at 359.664,-14.494 h1.27
  text "3" at 366.014,-14.494 h1.27
  text "QUALITY RELEASE REPORT" at 305.181,-17.542 h1.27
  text "OTHER" at 345.694,-17.542 h1.27
  text "PER ORDER" at 354.203,-17.669 h1.27
  text "X" at 343.027,-17.796 h1.52
  text "NONE" at 305.181,-20.59 h1.27
  text "REQUIRED" at 322.961,-20.59 h1.27
  text "PER ORDER" at 345.821,-20.59 h1.27
  text "ELECTRICAL TEST:" at 261.62,-20.717 h1.52
  text "X" at 320.294,-20.717 h1.52
  text "NONE" at 305.181,-23.638 h1.27
  text "1 SIDE" at 322.834,-23.638 h1.14
  text "2 SIDES" at 334.01,-23.638 h1.14
  text "MIN. PITCH" at 345.694,-23.638 h1.27
  text "0.50mm" at 359.283,-23.638 h1.27
  text "SURFACE MOUNT:" at 261.62,-23.765 h1.52
  text "X" at 331.775,-23.841 h1.52
  text "NONE" at 305.181,-26.686 h1.27
  text "FOIL" at 322.961,-26.686 h1.27
  text "LEGEND" at 334.391,-26.686 h1.27
  text "REFER" at 345.694,-26.686 h1.27
  text "MANUFACTURER'S ID/LOGO:" at 261.62,-26.813 h1.52
  text "ISO9001/AS3901" at 308.991,-29.734 h1.27
  text "NONE" at 345.694,-29.734 h1.27
  text "MANUFACTURER'S ACCREDITATION:" at 261.62,-29.861 h1.52
  text "X" at 306.324,-29.861 h1.52
  text "PER ORDER" at 305.181,-32.782 h1.27
  text "REFER" at 322.961,-32.782 h1.27
  text "PACKAGING AND HANDLING:" at 261.62,-32.909 h1.52
  text "X" at 302.514,-33.036 h1.52
Sheet:
  drawing of 1882 lines, arcs and shapes, not listed
  text "1" at 3.717,207.391 h1.78
  text "2" at 52.756,207.391 h1.78
  text "3" at 102.015,207.391 h1.78
  text "4" at 151.308,207.391 h1.78
  text "5" at 200.584,207.391 h1.78
  text "6" at 249.606,207.391 h1.78
  text "7" at 299.136,207.391 h1.78
  text "8" at 348.158,207.391 h1.78
  text "A" at -18.415,173.406 h1.78
  text "A" at 370.205,173.406 h1.78
  text "B" at -18.415,102.794 h1.78
  text "B" at 370.205,102.794 h1.78
  text "C" at -18.415,32.182 h1.78
  text "C" at 370.205,32.182 h1.78
  text "D" at -18.415,-37.922 h1.78
  text "D" at 370.205,-37.922 h1.78
  text "ENGINEER:" at 255.27,-38.1 h1.14
  text "TITLE:" at 293.37,-38.1 h1.14
  text "PCB DESIGNER:" at 255.27,-45.593 h1.14
  text "DATE:" at 255.27,-53.34 h1.14
  text "PART NO.:" at 293.37,-53.34 h1.14
  text "REV:" at 346.71,-53.34 h1.14
  text "Altium Limited" at 222.25,-55.88 h1.78
  text ".PRINT_DATE" at 256.54,-56.388 h1.78
  text "12a Rodborough Rd" at 222.25,-58.42 h1.78
  text "Frenchs Forest" at 222.25,-60.96 h1.78
  text "FILE NAME:" at 255.27,-60.96 h1.14
  text "DWG NO:" at 293.37,-60.96 h1.14
  text "SCALE:" at 346.71,-60.96 h1.14
  text "NSW 2086" at 222.25,-63.5 h1.78
  text ".PCB_FILE_NAME_NO_PATH" at 256.54,-64.008 h1.78
  text "1" at 3.717,-69.469 h1.78
  text "2" at 52.756,-69.469 h1.78
  text "3" at 102.015,-69.469 h1.78
  text "4" at 151.308,-69.469 h1.78
  text "5" at 200.584,-69.469 h1.78
  text "6" at 249.606,-69.469 h1.78
  text "7" at 299.136,-69.469 h1.78
  text "8" at 348.158,-69.469 h1.78
Drill Drawing:
  text ".Legend" at 0,-8 h0.75

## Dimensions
0,0 to 69,0 on Dimensions
0,0 to 0.001,77 on Dimensions
34.5,-69.801 to 34.5,84 on Dimensions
